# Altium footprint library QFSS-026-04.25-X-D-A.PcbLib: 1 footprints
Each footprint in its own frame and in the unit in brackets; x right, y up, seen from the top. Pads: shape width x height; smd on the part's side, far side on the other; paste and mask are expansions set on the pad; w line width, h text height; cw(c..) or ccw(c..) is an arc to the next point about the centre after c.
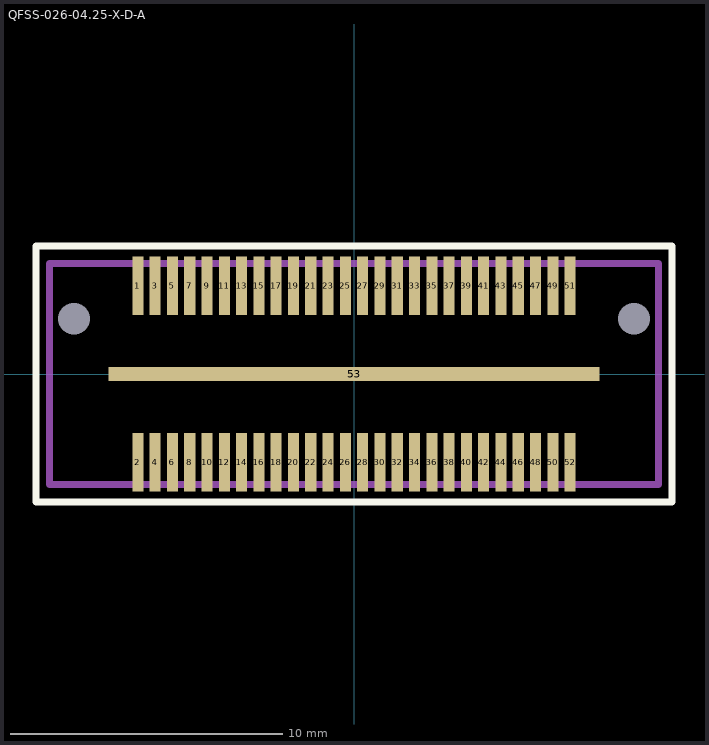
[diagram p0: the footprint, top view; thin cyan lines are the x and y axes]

## QFSS-026-04.25-X-D-A [mil]
pads (55):
  rect 16x85 smd mask+2: 1(-312.5,127.5) 2(-312.5,-127.5) 3(-287.5,127.5) 4(-287.5,-127.5) 5(-262.5,127.5) 6(-262.5,-127.5) 7(-237.5,127.5) 8(-237.5,-127.5) 9(-212.5,127.5) 10(-212.5,-127.5) 11(-187.5,127.5) 12(-187.5,-127.5) 13(-162.5,127.5) 14(-162.5,-127.5) 15(-137.5,127.5) 16(-137.5,-127.5) 17(-112.5,127.5) 18(-112.5,-127.5) 19(-87.5,127.5) 20(-87.5,-127.5) 21(-62.5,127.5) 22(-62.5,-127.5) 23(-37.5,127.5) 24(-37.5,-127.5) 25(-12.5,127.5) 26(-12.5,-127.5) 27(12.5,127.5) 28(12.5,-127.5) 29(37.5,127.5) 30(37.5,-127.5) 31(62.5,127.5) 32(62.5,-127.5) 33(87.5,127.5) 34(87.5,-127.5) 35(112.5,127.5) 36(112.5,-127.5) 37(137.5,127.5) 38(137.5,-127.5) 39(162.5,127.5) 40(162.5,-127.5) 41(187.5,127.5) 42(187.5,-127.5) 43(212.5,127.5) 44(212.5,-127.5) 45(237.5,127.5) 46(237.5,-127.5) 47(262.5,127.5) 48(262.5,-127.5) 49(287.5,127.5) 50(287.5,-127.5) 51(312.5,127.5) 52(312.5,-127.5)
  rect 710x20 smd mask+2: 53(0,0)
  round 0 hole 46 unplated: 54(-405,80) 55(405,80)
Top Overlay:
  lines w10: -460,-185 460,-185 460,185 -460,185 -460,-185
Mechanical 1:
  lines w10: -440,-160 440,-160 440,160 -440,160 -440,-160
  text "J1" at -17.57,-18 h30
